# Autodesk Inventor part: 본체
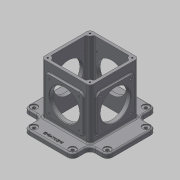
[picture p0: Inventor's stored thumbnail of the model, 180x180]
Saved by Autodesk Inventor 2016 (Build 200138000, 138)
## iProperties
Created: 2018-09
Part Number: 본체
Material: 일반
Document SubType Name: Modeling
Designer: mduedu
Density: 1 g/cm^3
Appearance: 기본값
Author: mduedu
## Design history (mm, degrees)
sketch "스케치1"
  geometry: L1 (90, 52.5)-(-90, 52.5); L2 (-90, 52.5)-(-90, -52.5); L3 (-90, -52.5)-(90, -52.5); L4 (90, -52.5)-(90, 52.5); L5 (90, 52.5)-(-90, -52.5); L6 (-90, 52.5)-(90, -52.5); L7 (-52.5, -90)-(52.5, -90); L8 (52.5, -90)-(52.5, 90); L9 (52.5, 90)-(-52.5, 90); L10 (-52.5, 90)-(-52.5, -90); L11 (-52.5, -90)-(52.5, 90); L12 (52.5, -90)-(-52.5, 90); 1 further point
  constraints: 24 end point, 4 midpoint, 4 parallel, 2 horizontal, 2 perpendicular
  dimensions: "d0" = 180 distance of L3.end L2.end; "d1" = 105 distance of L2.end L1.end; "d105" = 105 distance of L9.end L8.end; "d106" = 180 distance of L8.end L7.end
extrude "돌출1" new body sketch "스케치1" distance "d2" = 10; taper "d3" = 0 deg
fillet "모깎기16" dims "d107" = 11
sketch "스케치2"
  geometry: L1 (-52.5, -52.5)-(52.5, -52.5); L2 (52.5, -52.5)-(52.5, 52.5); L3 (52.5, 52.5)-(-52.5, 52.5); L4 (-52.5, 52.5)-(-52.5, -52.5); L5 (-52.5, -52.5)-(52.5, 52.5); L6 (52.5, -52.5)-(-52.5, 52.5); 1 further point
  constraints: 12 end point, 2 midpoint, 2 parallel, 1 horizontal, 1 perpendicular
  dimensions: "d4" = 105 distance of L3.end L2.end; "d5" = 105 distance of L2.end L1.end
extrude "돌출2" join sketch "스케치2" distance "d6" = 110; taper "d7" = 0 deg
sketch "스케치14"
  geometry: L1 (-52.5, 52.5)-(52.5, 52.5) reference; L2 (52.5, 52.5)-(52.5, -52.5) reference; L3 (52.5, -52.5)-(-52.5, -52.5) reference; L4 (-52.5, -52.5)-(-52.5, 52.5) reference; L5 (46.5, 46.5)-(-46.5, 46.5); L6 (-46.5, 46.5)-(-46.5, -46.5); L7 (-46.5, -46.5)-(46.5, -46.5); L8 (46.5, -46.5)-(46.5, 46.5); 1 further point
  constraints: 8 end point, 3 other
  dimensions: "d85" = 6 distance between parallel lines of L5 L1
extrude "돌출10" cut sketch "스케치14" stored distance "d86" = 10; taper "d87" = 0 deg
fillet "모깎기1" dims "d12" = 7
sketch "스케치15"
  geometry: A1 r 7 centre (-45.5, 45.5) between (-45.5, 52.5) and (-52.5, 45.5) reference; A2 r 7 centre (45.5, 45.5) between (52.5, 45.5) and (45.5, 52.5) reference; A3 r 7 centre (45.5, -45.5) between (45.5, -52.5) and (52.5, -45.5) reference; A4 r 7 centre (-45.5, -45.5) between (-52.5, -45.5) and (-45.5, -52.5) reference; 5 further points
  constraints: 4 coincident, 4 vertical alignment, 8 other
extrude "돌출11" join sketch "스케치15" stored distance "d88" = 10; taper "d89" = 0 deg
fillet "모깎기15" dims "d90" = 3
sketch "스케치6"
  geometry: L1 (50, 20)-(130, 20); L2 (130, 20)-(130, 100); L3 (130, 100)-(50, 100); L4 (50, 100)-(50, 20); L5 (50, 20)-(130, 100); L6 (130, 20)-(50, 100); L7 (0, 0)-(180, 0) reference; 4 further points
  constraints: 12 end point, 4 midpoint, 2 parallel, 1 horizontal, 1 perpendicular, 1 vertical alignment
  dimensions: "d25" = 80 distance of L3.end L2.end; "d26" = 80 distance of L2.end L1.end; "d27" = 60 distance of point (90, 0) point (90, 60)
extrude "돌출6" join sketch "스케치6" distance "d28" = 3; taper "d29" = 0 deg
fillet "모깎기7" dims "d30" = 8
sketch "스케치7"
  geometry: C1 r 32.5 at (90, 60); 1 further point
  constraints: 1 centre point, 1 vertical alignment
  dimensions: "d32" = 65 diameter of C1; "d33" = 60 distance of C1.centre point (90, 0)
extrude "돌출7" cut sketch "스케치7" stored distance "d34" = 3; taper "d35" = 0 deg
fillet "모깎기9" dims "d36" = 3
sketch "스케치8"
  geometry: L1 (5.5, 10)-(85.5, 10); L2 (85.5, 10)-(85.5, 90); L3 (85.5, 90)-(5.5, 90); L4 (5.5, 90)-(5.5, 10); L5 (5.5, 10)-(85.5, 90); L6 (85.5, 10)-(5.5, 90); L7 (-7, -10)-(98, -10) reference; C1 r 32.5 at (45.5, 50); 4 further points
  constraints: 12 end point, 4 midpoint, 2 parallel, 1 centre point, 1 coincident, 1 horizontal, 1 perpendicular, 1 vertical alignment
  dimensions: "d37" = 80 distance of L3.end L2.end; "d38" = 80 distance of L2.end L1.end; "d39" = 60 distance from line of point (45.5, 50) L7; "d40" = 65 diameter of C1
extrude "돌출8" join sketch "스케치8" distance "d41" = 3; taper "d42" = 0 deg
fillet "모깎기10" dims "d43" = 8
extrude "돌출9" cut sketch "스케치8" stored distance "d44" = 3; taper "d45" = 0 deg
fillet "모깎기11" dims "d46" = 3
sketch "스케치9"
  geometry: L1 (50, 92)-(50, 28) reference; L2 (58, 20)-(122, 20) reference; L3 (130, 28)-(130, 92) reference; L4 (122, 100)-(58, 100) reference; C1 r 32.5 at (90, 60) reference; A1 r 8 centre (58, 92) between (58, 100) and (50, 92) reference; A2 r 8 centre (58, 28) between (50, 28) and (58, 20) reference; A3 r 8 centre (122, 28) between (122, 20) and (130, 28) reference; A4 r 8 centre (122, 92) between (130, 92) and (122, 100) reference; 5 further points
  constraints: 4 coincident
hole "구멍1" sketch "스케치9" at (58, 92), (122, 92), (122, 28), (58, 28) diameter "d47" = 3.242; stored, may be unused: countersink angle "d51" = 90 deg, drill point angle "d53" = 118 deg; dims "d48" = 6, "d49" = 4, "d50" = 2, "d52" = 9
sketch "스케치10"
  geometry: L1 (13.5, 10)-(77.5, 10) reference; L2 (85.5, 18)-(85.5, 82) reference; L3 (77.5, 90)-(13.5, 90) reference; L4 (5.5, 82)-(5.5, 18) reference; C1 r 32.5 at (45.5, 50) reference; A1 r 8 centre (13.5, 18) between (5.5, 18) and (13.5, 10) reference; A2 r 8 centre (77.5, 18) between (77.5, 10) and (85.5, 18) reference; A3 r 8 centre (77.5, 82) between (85.5, 82) and (77.5, 90) reference; A4 r 8 centre (13.5, 82) between (13.5, 90) and (5.5, 82) reference; 5 further points
  constraints: 4 coincident
hole "구멍2" sketch "스케치10" at (13.5, 82), (77.5, 82), (77.5, 18), (13.5, 18) diameter "d54" = 3.242; stored, may be unused: countersink angle "d58" = 90 deg, drill point angle "d60" = 118 deg; dims "d55" = 6, "d56" = 4, "d57" = 2, "d59" = 9
fillet "모깎기12" dims "d68" = 11
sketch "스케치16"
  geometry: A1 r 11 centre (-79, 41.5) between (-79, 52.5) and (-90, 41.5) reference; A2 r 11 centre (-79, -41.5) between (-90, -41.5) and (-79, -52.5) reference; A3 r 11 centre (79, 41.5) between (90, 41.5) and (79, 52.5) reference; A4 r 11 centre (79, -41.5) between (79, -52.5) and (90, -41.5) reference; A5 r 11 centre (-41.5, 79) between (-41.5, 90) and (-52.5, 79) reference; A6 r 11 centre (41.5, 79) between (52.5, 79) and (41.5, 90) reference; A7 r 11 centre (41.5, -79) between (41.5, -90) and (52.5, -79) reference; A8 r 11 centre (-41.5, -79) between (-52.5, -79) and (-41.5, -90) reference; 9 further points
  constraints: 8 coincident
hole "구멍5" sketch "스케치16" at (-79, 41.5), (79, 41.5), (79, -41.5), (-79, -41.5), (41.5, 79), (-41.5, 79), (-41.5, -79), (41.5, -79) diameter "d91" = 6.6; stored, may be unused: countersink angle "d95" = 90 deg, drill point angle "d97" = 118 deg; dims "d92" = 6, "d93" = 15, "d94" = 2, "d96" = 8
fillet "모깎기13" dims "d77" = 3
chamfer "모따기1" distance "d79" = 1; stored, may be unused: second distance "d80" = 2, angle "d81" = 45 deg
sketch "스케치17"
  geometry: A1 r 7 centre (-45.5, 45.5) between (-45.5, 52.5) and (-52.5, 45.5) reference; A2 r 7 centre (-45.5, -45.5) between (-52.5, -45.5) and (-45.5, -52.5) reference; A3 r 7 centre (45.5, -45.5) between (45.5, -52.5) and (52.5, -45.5) reference; A4 r 7 centre (45.5, 45.5) between (52.5, 45.5) and (45.5, 52.5) reference; 5 further points
  constraints: 4 coincident
hole "구멍6" sketch "스케치17" at (-45.5, 45.5), (45.5, 45.5), (45.5, -45.5), (-45.5, -45.5) diameter "d98" = 3.242; stored, may be unused: countersink angle "d102" = 90 deg, drill point angle "d104" = 118 deg; dims "d99" = 8, "d100" = 15, "d101" = 2, "d103" = 10
sketch "스케치13"
  geometry: L1 (90, -41.5)-(90, 41.5) reference; 2 further points
  constraints: 1 horizontal alignment, 1 other
  dimensions: "d82" = 11 distance from line of point (79, 0) L1
feature "엠보싱1" sketch "스케치13" dims "d0" = 180, "d1" = 105, "d83" = 0.5, "d84" = 0
node "솔리드1"
mirror "대칭1"
mirror "대칭4"
mirror "대칭2"
mirror "대칭5"
node "투영된 루프2"
node "투영된 루프3"
node "투영된 루프6"
